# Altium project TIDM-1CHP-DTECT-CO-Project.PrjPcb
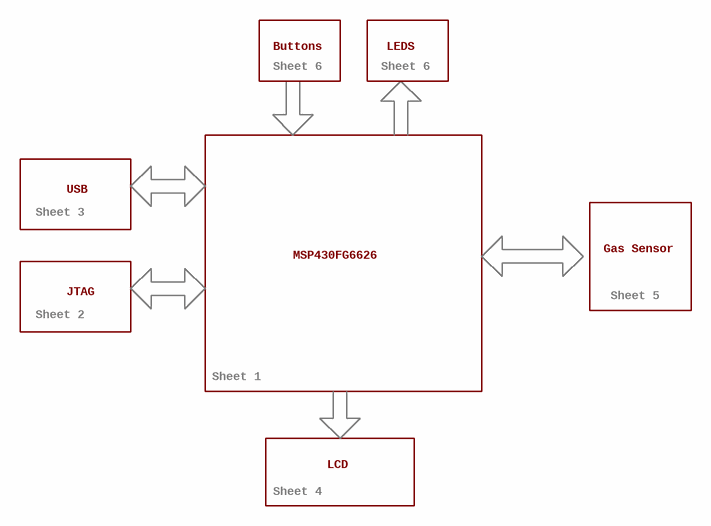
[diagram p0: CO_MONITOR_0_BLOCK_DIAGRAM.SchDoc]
CopyrightYear: 2016; EVM_orderable: Not Orderable; PCB_Layout: Ricardo Zepeda; PCB_Rev: 1.0; PRJ_Customer: Public Release; PRJ_Engineer: Ricardo Zepeda; PRJ_Title: MSP430 Single-Chip, Portable, CO Detector; SCH_Rev: 1.0; TechSupport: http://www.ti.com/support; TID: TIDM-1CHP-DTECT-CO
8 sheets, 116 parts. Net scope: global (net labels, ports and power ports of the same name join across sheets).
Board files: CO_MONITOR_LAYOUT_MAIN.PcbDoc, CO_MONITOR_LAYOUT_BACKUP.PcbDoc
Sheets:
  CO_MONITOR_0_BLOCK_DIAGRAM.SchDoc
  CO_MONITOR_1_MSP430FG6626.SchDoc
  CO_MONITOR_2_JTAG_SBW.SchDoc
  CO_MONITOR_3_USB_SUBCIRCUIT.SchDoc
  CO_MONITOR_4_LCD.SchDoc
  CO_MONITOR_5_GASDETECTION_SUBCIRCUIT.SchDoc
  CO_MONITOR_6_POWER_SUPPLY.SchDoc
  CO_MONITOR_7_MISCELLANEOUS.SchDoc

## Sheet CO_MONITOR_0_BLOCK_DIAGRAM.SchDoc: CO_MONITOR_0_BLOCK_DIAGRAM.SchDoc
size 431 x 279 mm; DrawnBy: Ricardo Zepeda; SheetNumber: 1; SheetTotal: 8; PageSetup: Record=PageOptions¦CenterHorizontal=True¦CenterVertical=True¦PrintScale=1.00¦XCorrection=1.00¦YCorrection=1.00¦PrintKind=0¦BorderSize=5000000¦LeftOffset=0¦BottomOffset=0¦Orientation=2¦PaperLength=1000¦PaperWidth=1000¦Scale=100¦PaperSource=15¦PrintQuality=600¦MediaType=1¦DitherType=10¦PaperKind=Letter¦PrintScaleMode=1

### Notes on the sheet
- Buttons
- Sheet 6
- LEDS
- Sheet 3
- USB
- MSP430FG6626
- Gas Sensor
- Sheet 2
- JTAG
- Sheet 5
- Sheet 1
- LCD
- Sheet 4

## Sheet CO_MONITOR_1_MSP430FG6626.SchDoc: CO_MONITOR_1_MSP430FG6626.SchDoc
size 431 x 279 mm; DrawnBy: Ricardo Zepeda; SheetNumber: 2; SheetTotal: 8; PageSetup: Record=PageOptions¦CenterHorizontal=True¦CenterVertical=True¦PrintScale=1.00¦XCorrection=1.00¦YCorrection=1.00¦PrintKind=0¦BorderSize=5000000¦LeftOffset=0¦BottomOffset=0¦Orientation=2¦PaperLength=1000¦PaperWidth=1000¦Scale=100¦PaperSource=15¦PrintQuality=600¦MediaType=1¦DitherType=10¦PaperKind=Letter¦PrintScaleMode=1
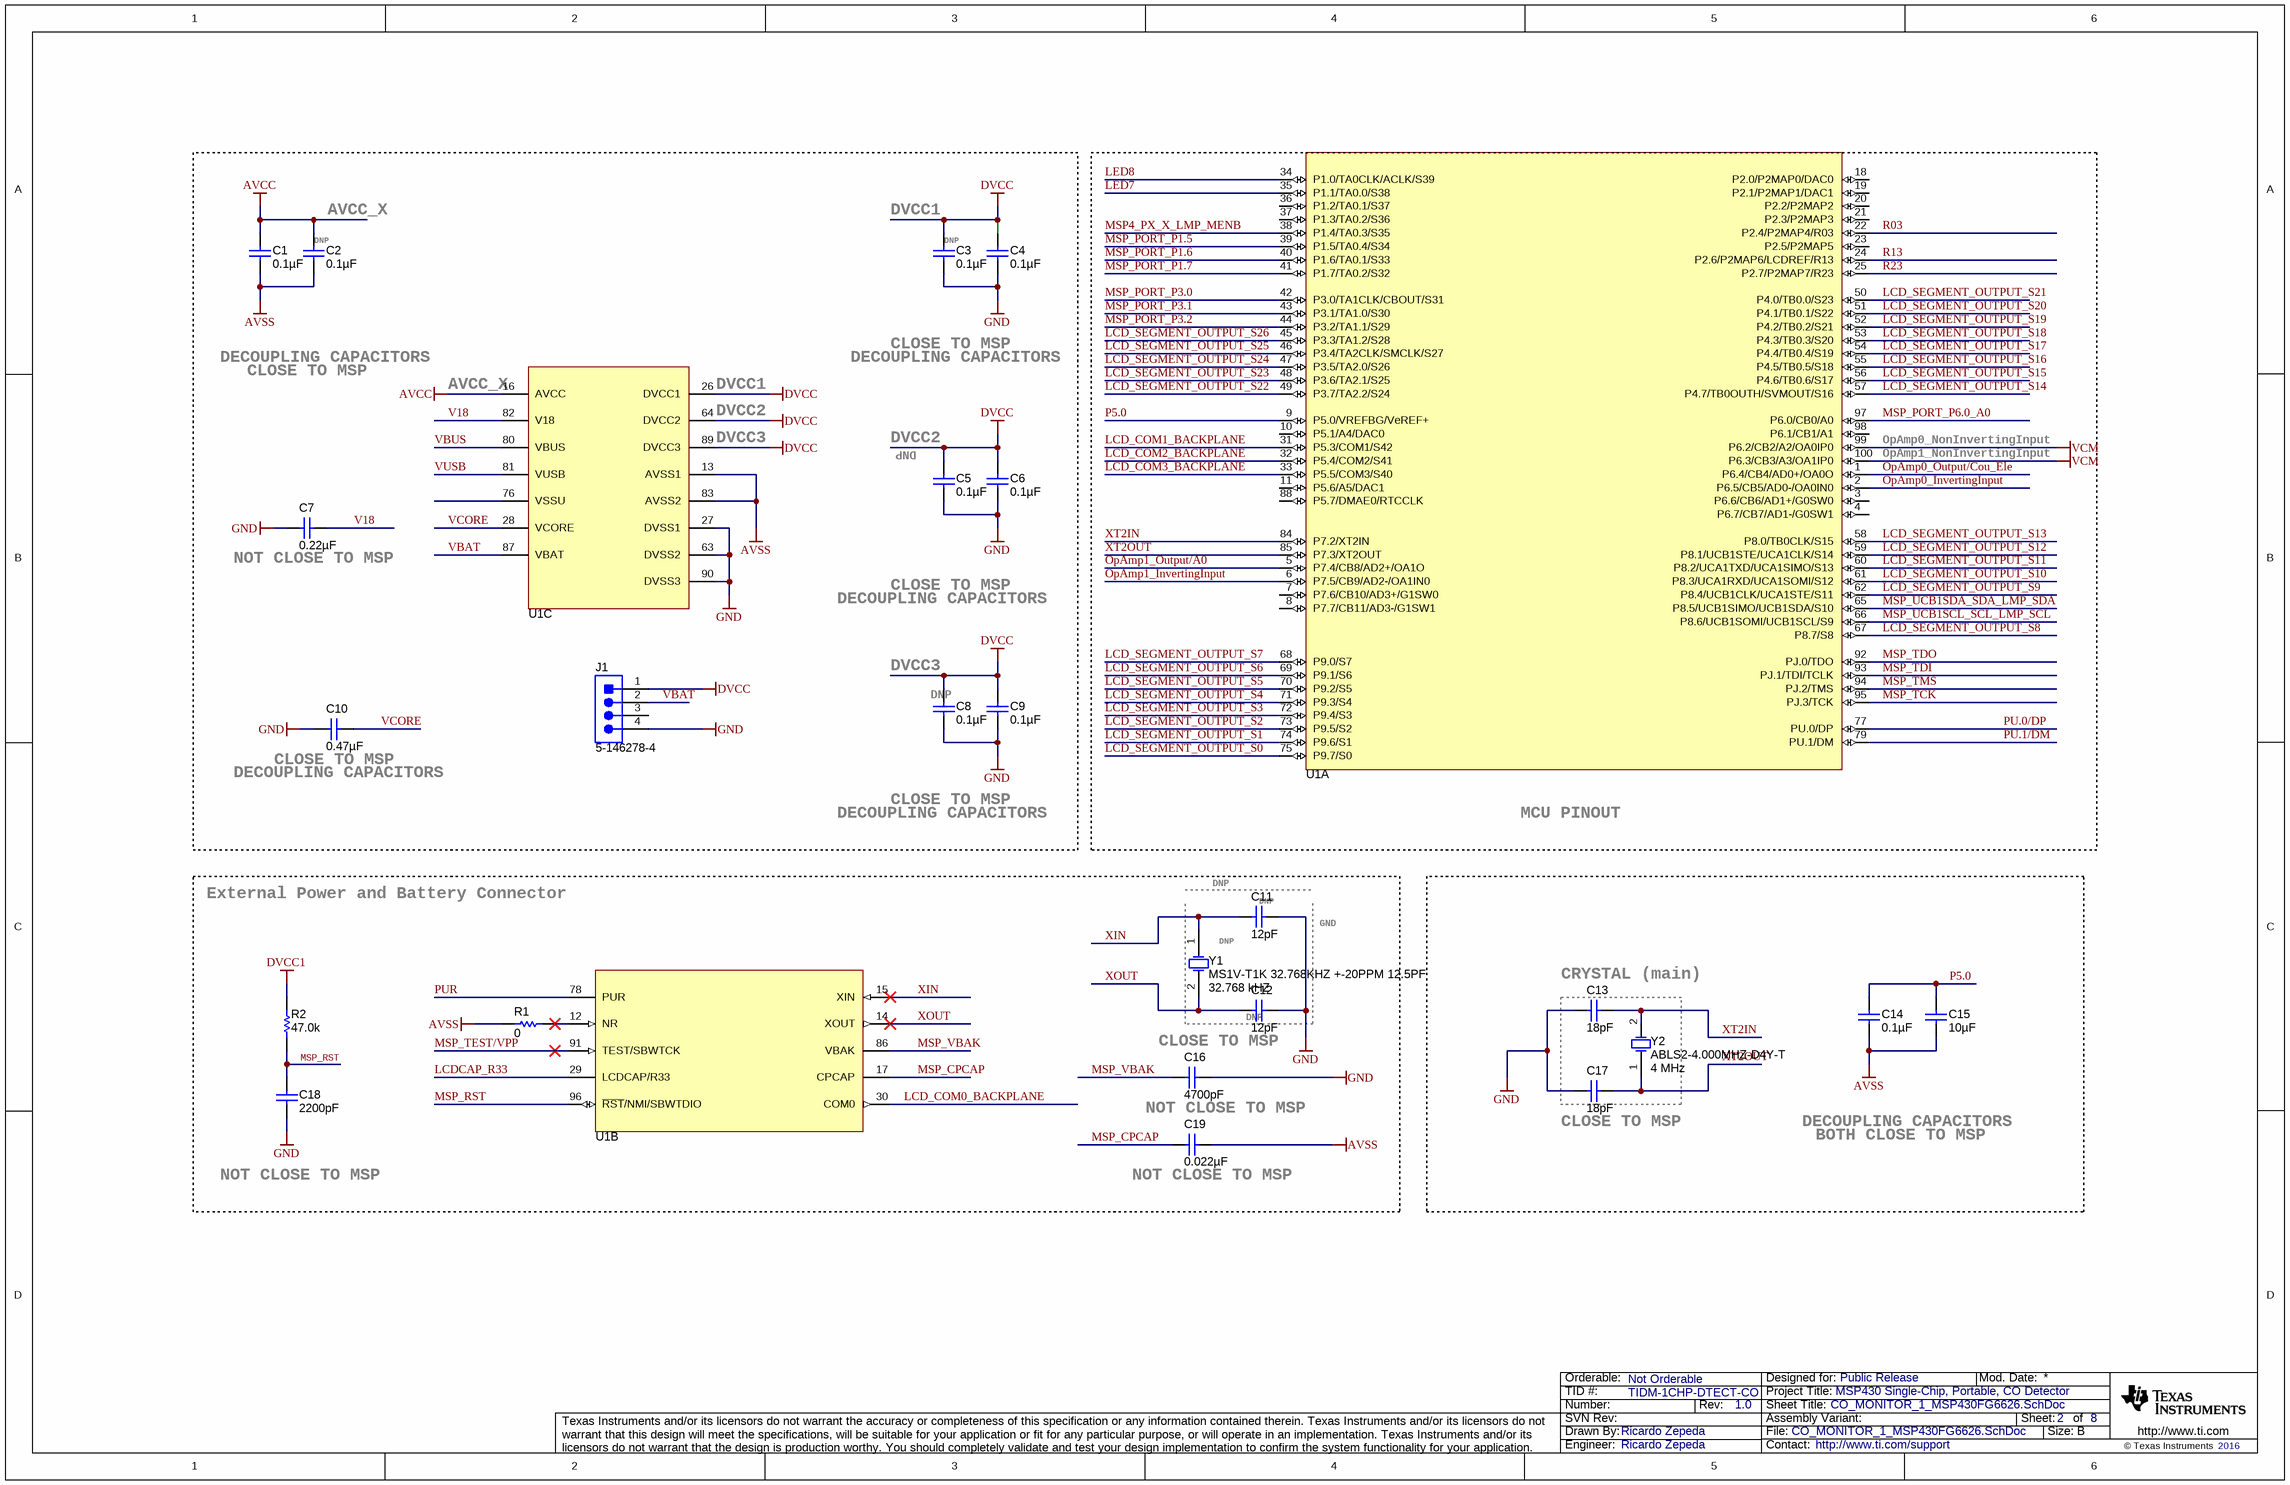
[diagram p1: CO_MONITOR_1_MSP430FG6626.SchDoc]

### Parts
C1  ValueDisplayed: 0.1µF  [1206_190]  (hidden comment: C3216NP01H104J160AA)
C2  ValueDisplayed: 0.1µF  [1206_190]  (hidden comment: C3216NP01H104J160AA)
C3  ValueDisplayed: 0.1µF  [1206_190]  (hidden comment: C3216NP01H104J160AA)
C4  ValueDisplayed: 0.1µF  [1206_190]  (hidden comment: C3216NP01H104J160AA)
C5  ValueDisplayed: 0.1µF  [1206_190]  (hidden comment: C3216NP01H104J160AA)
C6  ValueDisplayed: 0.1µF  [1206_190]  (hidden comment: C3216NP01H104J160AA)
C7  ValueDisplayed: 0.22µF  [0603]  (hidden comment: C1608X7R1H224K080AB)
C8  ValueDisplayed: 0.1µF  [1206_190]  (hidden comment: C3216NP01H104J160AA)
C9  ValueDisplayed: 0.1µF  [1206_190]  (hidden comment: C3216NP01H104J160AA)
C10  ValueDisplayed: 0.47µF  [0603]  (hidden comment: GRM188R61C474KA93D)
C11  ValueDisplayed: 12pF  [0603]  (hidden comment: C1608C0G1H120J)
C12  ValueDisplayed: 12pF  [0603]  (hidden comment: C1608C0G1H120J)
C13  ValueDisplayed: 18pF  [0805]  (hidden comment: C0805C180J5GACTU)
C14  ValueDisplayed: 0.1µF  [1206_190]  (hidden comment: C3216NP01H104J160AA)
C15  ValueDisplayed: 10µF  [0603]  (hidden comment: GRM188R60J106ME84)
C16  ValueDisplayed: 4700pF  [0603]  (hidden comment: C0603C472J5RACTU)
C17  ValueDisplayed: 18pF  [0805]  (hidden comment: C0805C180J5GACTU)
C18  ValueDisplayed: 2200pF  [0603]  (hidden comment: GRM188R71C222KA01D)
C19  ValueDisplayed: 0.022µF  [0603]  (hidden comment: GRM188R71H223KA01D)
J1  5-146278-4  [TE_5-146278-4]
R1  ValueDisplayed: 0  [0603]  (hidden comment: CRCW06030000Z0EA)
R2  ValueDisplayed: 47.0k  [0603]  (hidden comment: RT0603BRD0747KL)
U1  MSP430FG6626IPZR  [PZ0100A_N]  (value not drawn)  (parts A,B,C of 3)
Y1  MS1V-T1K 32.768KHZ +-20PPM 12.5PF  Frequency: 32.768 kHZ  [XTAL_MS1V-T1K]
Y2  ABLS2-4.000MHZ-D4Y-T  Frequency: 4 MHz  [ABRACON_ABLS2]

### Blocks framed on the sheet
MCU PINOUT: U1
CRYSTAL (main): C13 C17 Y2

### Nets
AVCC: C1.1 C2.1 U1.16(AVCC)
AVSS: C1.2 C2.2 C14.2 C15.2 C19.1 R1.1 U1.13(AVSS1) U1.83(AVSS2)
DVCC: C3.1 C4.1 C5.1 C6.1 C8.1 C9.1 J1.1 U1.26(DVCC1) U1.64(DVCC2) U1.89(DVCC3)
DVCC1: R2.2
GND: C3.2 C4.2 C5.2 C6.2 C7.2 C8.2 C9.2 C10.2 C11.1 C12.1 C13.2 C16.1 C17.2 C18.2 J1.4 U1.27(DVSS1) U1.63(DVSS2) U1.90(DVSS3)
VCM: U1.99(P6.2/CB2/A2/OA0IP0) U1.100(P6.3/CB3/A3/OA1IP0)
LCD_COM0_BACKPLANE: U1.30(COM0)
LCD_COM1_BACKPLANE: U1.31(P5.3/COM1/S42)
LCD_COM2_BACKPLANE: U1.32(P5.4/COM2/S41)
LCD_COM3_BACKPLANE: U1.33(P5.5/COM3/S40)
LCD_SEGMENT_OUTPUT_S0: U1.75(P9.7/S0)
LCD_SEGMENT_OUTPUT_S1: U1.74(P9.6/S1)
LCD_SEGMENT_OUTPUT_S2: U1.73(P9.5/S2)
LCD_SEGMENT_OUTPUT_S3: U1.72(P9.4/S3)
LCD_SEGMENT_OUTPUT_S4: U1.71(P9.3/S4)
LCD_SEGMENT_OUTPUT_S5: U1.70(P9.2/S5)
LCD_SEGMENT_OUTPUT_S6: U1.69(P9.1/S6)
LCD_SEGMENT_OUTPUT_S7: U1.68(P9.0/S7)
LCD_SEGMENT_OUTPUT_S8: U1.67(P8.7/S8)
LCD_SEGMENT_OUTPUT_S9: U1.62(P8.4/UCB1CLK/UCA1STE/S11)
LCD_SEGMENT_OUTPUT_S10: U1.61(P8.3/UCA1RXD/UCA1SOMI/S12)
LCD_SEGMENT_OUTPUT_S11: U1.60(P8.2/UCA1TXD/UCA1SIMO/S13)
LCD_SEGMENT_OUTPUT_S12: U1.59(P8.1/UCB1STE/UCA1CLK/S14)
LCD_SEGMENT_OUTPUT_S13: U1.58(P8.0/TB0CLK/S15)
LCD_SEGMENT_OUTPUT_S14: U1.57(P4.7/TB0OUTH/SVMOUT/S16)
LCD_SEGMENT_OUTPUT_S15: U1.56(P4.6/TB0.6/S17)
LCD_SEGMENT_OUTPUT_S16: U1.55(P4.5/TB0.5/S18)
LCD_SEGMENT_OUTPUT_S17: U1.54(P4.4/TB0.4/S19)
LCD_SEGMENT_OUTPUT_S18: U1.53(P4.3/TB0.3/S20)
LCD_SEGMENT_OUTPUT_S19: U1.52(P4.2/TB0.2/S21)
LCD_SEGMENT_OUTPUT_S20: U1.51(P4.1/TB0.1/S22)
LCD_SEGMENT_OUTPUT_S21: U1.50(P4.0/TB0.0/S23)
LCD_SEGMENT_OUTPUT_S22: U1.49(P3.7/TA2.2/S24)
LCD_SEGMENT_OUTPUT_S23: U1.48(P3.6/TA2.1/S25)
LCD_SEGMENT_OUTPUT_S24: U1.47(P3.5/TA2.0/S26)
LCD_SEGMENT_OUTPUT_S25: U1.46(P3.4/TA2CLK/SMCLK/S27)
LCD_SEGMENT_OUTPUT_S26: U1.45(P3.3/TA1.2/S28)
LCDCAP_R33: U1.29(LCDCAP/R33)
LED7: U1.35(P1.1/TA0.0/S38)
LED8: U1.34(P1.0/TA0CLK/ACLK/S39)
MSP4_PX_X_LMP_MENB: U1.38(P1.4/TA0.3/S35)
MSP_CPCAP: C19.2 U1.17(CPCAP)
MSP_PORT_P1.5: U1.39(P1.5/TA0.4/S34)
MSP_PORT_P1.6: U1.40(P1.6/TA0.1/S33)
MSP_PORT_P1.7: U1.41(P1.7/TA0.2/S32)
MSP_PORT_P3.0: U1.42(P3.0/TA1CLK/CBOUT/S31)
MSP_PORT_P3.1: U1.43(P3.1/TA1.0/S30)
MSP_PORT_P3.2: U1.44(P3.2/TA1.1/S29)
MSP_PORT_P6.0_A0: U1.97(P6.0/CB0/A0)
MSP_RST: C18.1 R2.1 U1.96(~{RST}/NMI/SBWTDIO)
MSP_TCK: U1.95(PJ.3/TCK)
MSP_TDI: U1.93(PJ.1/TDI/TCLK)
MSP_TDO: U1.92(PJ.0/TDO)
MSP_TEST/VPP: U1.91(TEST/SBWTCK)
MSP_TMS: U1.94(PJ.2/TMS)
MSP_UCB1SCL_SCL_LMP_SCL: U1.66(P8.6/UCB1SOMI/UCB1SCL/S9)
MSP_UCB1SDA_SDA_LMP_SDA: U1.65(P8.5/UCB1SIMO/UCB1SDA/S10)
MSP_VBAK: C16.2 U1.86(VBAK)
OpAmp0_InvertingInput: U1.2(P6.5/CB5/AD0-/OA0IN0)
OpAmp0_Output/Cou_Ele: U1.1(P6.4/CB4/AD0+/OA0O)
OpAmp1_InvertingInput: U1.6(P7.5/CB9/AD2-/OA1IN0)
OpAmp1_Output/A0: U1.5(P7.4/CB8/AD2+/OA1O)
P5.0: C14.1 C15.1 U1.9(P5.0/VREFBG/VeREF+)
PU.0/DP: U1.77(PU.0/DP)
PU.1/DM: U1.79(PU.1/DM)
PUR: U1.78(PUR)
R03: U1.22(P2.4/P2MAP4/R03)
R13: U1.24(P2.6/P2MAP6/LCDREF/R13)
R23: U1.25(P2.7/P2MAP7/R23)
V18: C7.1 U1.82(V18)
VBAT: J1.2 U1.87(VBAT)
VBUS: U1.80(VBUS)
VCORE: C10.1 U1.28(VCORE)
VUSB: U1.81(VUSB)
XIN: C11.2 U1.15(XIN) Y1.1(OSC1)
XOUT: C12.2 U1.14(XOUT) Y1.2(OSC2)
XT2IN: C13.1 U1.84(P7.2/XT2IN) Y2.2(OSC2)
XT2OUT: C17.1 U1.85(P7.3/XT2OUT) Y2.1(OSC1)
NetR1_2: R1.2 U1.12(NR)

Not connected (* = marked no-connect by the designer): J1 3; U1 3(P6.6/CB6/AD1+/G0SW0) 4(P6.7/CB7/AD1-/G0SW1) 7(P7.6/CB10/AD3+/G1SW0) 8(P7.7/CB11/AD3-/G1SW1) 10(P5.1/A4/DAC0) 11(P5.6/A5/DAC1) 18(P2.0/P2MAP0/DAC0) 19(P2.1/P2MAP1/DAC1) 20(P2.2/P2MAP2) 21(P2.3/P2MAP3) 23(P2.5/P2MAP5) 36(P1.2/TA0.1/S37) 37(P1.3/TA0.2/S36) 76(VSSU) 88(P5.7/DMAE0/RTCCLK) 98(P6.1/CB1/A1)

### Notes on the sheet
- (near C2) AVCC_X
- (near C3) DVCC1
- (near C2) DNP
- (near C3) DNP
- DECOUPLING CAPACITORS
- CLOSE TO MSP
- (near U1) AVCC_X
- (near U1) DVCC1
- (near U1) DVCC2
- (near U1) DVCC3
- (near C5) DVCC2
- (near C5) DNP
- (near U1) OpAmp0_NonInvertingInput
- (near U1) OpAmp1_NonInvertingInput
- (near C7) NOT CLOSE TO MSP
- (near C8) DVCC3
- (near C8) DNP
- (near C10) CLOSE TO MSP
- (near C10) DECOUPLING CAPACITORS
- External Power and Battery Connector
- DNP
- (near C11) DNP
- (near Y1) DNP
- (near C11) GND
- (near C12) DNP
- NOT CLOSE TO MSP
- (near C17) CLOSE TO MSP
- BOTH CLOSE TO MSP
- (near C19) NOT CLOSE TO MSP

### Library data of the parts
C1-C6 C8 C9 C14 = C3216NP01H104J160AA: CAP, CERM, 0.1 µF, 50 V, +/- 5%, C0G/NP0, 1206_190; Manufacturer: TDK; Polarized: N; CompType: Capacitor; Value: 0.1uF; U/M: EA; Cap_F: 0.0000001; Tolerance_%: 5; Value1: Unknown; VDC_V: 50; Value2: 50V; TaMin_C: -55; TaMax_C: 150; Cap_Case: 1206
C7 = C1608X7R1H224K080AB: CAP, CERM, 0.22 µF, 50 V, +/- 10%, X7R, 0603; Manufacturer: TDK; Polarized: N; CompType: Capacitor; Value: 0.22uF; U/M: EA; Cap_F: 0.00000022; Tolerance_%: 10; Value1: Unknown; VDC_V: 50; Value2: 50V; TaMin_C: -55; TaMax_C: 125
C10 = GRM188R61C474KA93D: CAP, CERM, 0.47 µF, 16 V, +/- 10%, X5R, 0603; Manufacturer: MuRata; Polarized: N; CompType: Capacitor; Value: 0.47uF; U/M: EA; Cap_F: 0.00000047; Tolerance_%: 10; Value1: Unknown; VDC_V: 16; Value2: 16V; TaMin_C: -55; TaMax_C: 85
C11 C12 = C1608C0G1H120J: CAP, CERM, 12 pF, 50 V, +/- 5%, C0G/NP0, 0603; Manufacturer: TDK; Polarized: N; CompType: Capacitor; Value: 12pF; U/M: EA; Cap_F: 0.000000000012; Tolerance_%: 5; ESR_ohm: 0.3764; Value1: 0.3764 ohm; VDC_V: 50; Value2: 50V; TaMin_C: -55; TaMax_C: 125
C13 C17 = C0805C180J5GACTU: CAP, CERM, 18 pF, 50 V, +/- 5%, C0G/NP0, 0805; Manufacturer: Kemet; Polarized: N; CompType: Capacitor; Value: 18pF; U/M: EA; Cap_F: 0.000000000018; Tolerance_%: 5; ESR_ohm: 0.193; Value1: 0.193 ohm; VDC_V: 50; Value2: 50V; IRMS_A: 0.38; TaMin_C: -55; TaMax_C: 125
C15 = GRM188R60J106ME84: CAP, CERM, 10 µF, 6.3 V, +/- 20%, X5R, 0603; Manufacturer: MuRata; Polarized: N; CompType: Capacitor; Value: 10uF; U/M: EA; Cap_F: 0.00001; Tolerance_%: 20; Value1: Unknown; VDC_V: 6.3; Value2: 6.3V; TaMin_C: -55; TaMax_C: 85
C16 = C0603C472J5RACTU: CAP, CERM, 4700 pF, 50 V, +/- 5%, X7R, 0603; Manufacturer: Kemet; Polarized: N; CompType: Capacitor; Value: 4700pF; U/M: EA; Cap_F: 0.0000000047; Tolerance_%: 5; Value1: Unknown; VDC_V: 50; Value2: 50V; TaMin_C: -55; TaMax_C: 125
C18 = GRM188R71C222KA01D: CAP, CERM, 2200 pF, 16 V, +/- 10%, X7R, 0603; Manufacturer: MuRata; Polarized: N; CompType: Capacitor; Value: 2200pF; U/M: EA; Cap_F: 0.0000000022; Tolerance_%: 10; Value1: Unknown; VDC_V: 16; Value2: 16V; TaMin_C: -55; TaMax_C: 125
C19 = GRM188R71H223KA01D: CAP, CERM, 0.022 µF, 50 V, +/- 10%, X7R, 0603; Manufacturer: MuRata; Polarized: N; CompType: Capacitor; Value: 0.022uF; U/M: EA; Cap_F: 0.000000022; Tolerance_%: 10; Value1: Unknown; VDC_V: 50; Value2: 50V; TaMin_C: -55; TaMax_C: 125
J1 = 5-146278-4: Header, 100mil, 4x1, Tin, TH; Manufacturer: TE Connectivity; SymbolCreator: a0412235; U/M: EA
R1 = CRCW06030000Z0EA: RES, 0, 5%, 0.1 W, 0603; Manufacturer: Vishay-Dale; CompType: Resistor; Value: 0; Value_Code: 0000; Tolerance_%: 5; Power_W: 0.1; Value2: 0.1W; VDC_V: 75; TempCo: 200 ppm/C; EIA_Code: E24; U/M: EA
R2 = RT0603BRD0747KL: RES, 47.0 k, 0.1%, 0.1 W, 0603; Manufacturer: Yageo America; CompType: Resistor; Value: 47.0k; Res_ohm: 47000; Value_Code: 47k0; Tolerance_%: 0.1; Value2: 0.1W; VDC_V: 75; TempCo: 25 ppm/C; EIA_Code: E192; U/M: EA
U1 = MSP430FG6626IPZR: Mixed-Signal Microcontrollers, PZ0100A; Manufacturer: Texas Instruments; SymbolCreator: Altium; CompType: IC; U/M: EA
Y1 = MS1V-T1K 32.768KHZ +-20PPM 12.5PF: Tuning Fork Crystal, 32.768 kHz, 12.5 pF, SMD; Manufacturer: Micro Crystal AG; SymbolCreator: a0412235; U/M: EA; TaMin_C: -40; TaMax_C: 85; Frequency Stability: ±20ppm
Y2 = ABLS2-4.000MHZ-D4Y-T: Crystal, 4MHz, 18pF, SMD; Manufacturer: Abracon Corportation; SymbolCreator: a0412235; U/M: EA; TaMin_C: -40; TaMax_C: 85; Frequency Stability: ±30ppm

## Sheet CO_MONITOR_2_JTAG_SBW.SchDoc: CO_MONITOR_2_JTAG_SBW.SchDoc
size 431 x 279 mm; DrawnBy: Ricardo Zepeda; SheetNumber: 3; SheetTotal: 8; PageSetup: Record=PageOptions¦CenterHorizontal=True¦CenterVertical=True¦PrintScale=1.00¦XCorrection=1.00¦YCorrection=1.00¦PrintKind=0¦BorderSize=5000000¦LeftOffset=0¦BottomOffset=0¦Orientation=2¦PaperLength=1000¦PaperWidth=1000¦Scale=100¦PaperSource=15¦PrintQuality=600¦MediaType=1¦DitherType=10¦PaperKind=Letter¦PrintScaleMode=1
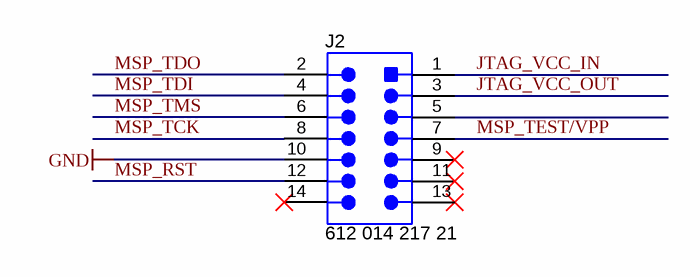
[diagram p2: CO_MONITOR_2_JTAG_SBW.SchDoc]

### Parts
J2  612 014 217 21  [WURTH_612_014_217_21]

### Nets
GND: J2.10
JTAG_VCC_IN: J2.1
JTAG_VCC_OUT: J2.3
MSP_RST: J2.12
MSP_TCK: J2.8
MSP_TDI: J2.4
MSP_TDO: J2.2
MSP_TEST/VPP: J2.7
MSP_TMS: J2.6

Not connected (* = marked no-connect by the designer): J2 5 9* 11* 13* 14*

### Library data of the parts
J2 = 612 014 217 21: Header (Shrouded), 2.54 mm, 7x2, Gold, R/A, TH; Manufacturer: Wurth Elektronik eiSos; SymbolCreator: a0412235; U/M: EA

## Sheet CO_MONITOR_3_USB_SUBCIRCUIT.SchDoc: CO_MONITOR_3_USB_SUBCIRCUIT.SchDoc
size 431 x 279 mm; DrawnBy: Ricardo Zepeda; SheetNumber: 4; SheetTotal: 8; PageSetup: Record=PageOptions¦CenterHorizontal=True¦CenterVertical=True¦PrintScale=1.00¦XCorrection=1.00¦YCorrection=1.00¦PrintKind=0¦BorderSize=5000000¦LeftOffset=0¦BottomOffset=0¦Orientation=2¦PaperLength=1000¦PaperWidth=1000¦Scale=100¦PaperSource=15¦PrintQuality=600¦MediaType=1¦DitherType=10¦PaperKind=Letter¦PrintScaleMode=1
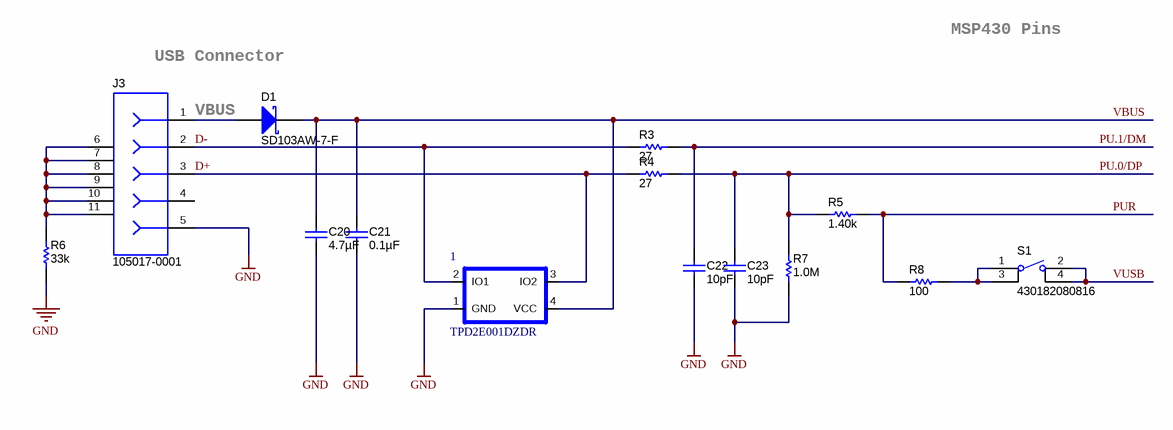
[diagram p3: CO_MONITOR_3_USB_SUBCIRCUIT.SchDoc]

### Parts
1  TPD2E001DZDR  [DZD]
C20  ValueDisplayed: 4.7µF  [0805]  (hidden comment: GRM21BC81E475KA12L)
C21  ValueDisplayed: 0.1µF  [0805]  (hidden comment: GRM21BR71H104KA01L)
C22  ValueDisplayed: 10pF  [0805]  (hidden comment: 08055A100JAT2A)
C23  ValueDisplayed: 10pF  [0805]  (hidden comment: 08055A100JAT2A)
D1  SD103AW-7-F  [SOD-123]
J3  105017-0001  [CONN_105017-0001]
R3  ValueDisplayed: 27  [0805_HV]  (hidden comment: CRCW080527R0JNEA)
R4  ValueDisplayed: 27  [0805_HV]  (hidden comment: CRCW080527R0JNEA)
R5  ValueDisplayed: 1.40k  [0805]  (hidden comment: CRCW08051K40FKEA)
R6  ValueDisplayed: 33k  [0805]  (hidden comment: CRCW080533K0JNEA)
R7  ValueDisplayed: 1.0M  [0805]  (hidden comment: CRCW08051M00JNEA)
R8  ValueDisplayed: 100  [0805]  (hidden comment: RT0805BRD07100RL)
S1  430182080816  [SW_430182080816]

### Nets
GND: 1.1(GND) C20.2 C21.2 C22.2 C23.2 J3.5 R6.1 R7.1
D+: 1.3(IO2) J3.3 R4.1
D-: 1.2(IO1) J3.2 R3.1
PU.0/DP: C23.1 R4.2 R5.1 R7.2
PU.1/DM: C22.1 R3.2
PUR: R5.2 R8.1
VBUS: 1.4(VCC) C20.1 C21.1 D1.1(K)
VUSB: S1.2 S1.4
NetD1_2: D1.2(A) J3.1
NetJ3_6: J3.6 J3.7 J3.8 J3.9 J3.10 J3.11 R6.2
NetR8_2: R8.2 S1.1 S1.3

Not connected (* = marked no-connect by the designer): J3 4

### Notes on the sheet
- USB Connector
- MSP430 Pins
- VBUS

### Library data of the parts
1 = TPD2E001DZDR: IC, Low-Capacitacnce 2-Chan ±15-kV ESD-Protection Array; Manufacturer: TI; Alternate Manufacturer: None; Area: 15.96 mm
C20 = GRM21BC81E475KA12L: CAP, CERM, 4.7 µF, 25 V, +/- 10%, X6S, 0805; Manufacturer: MuRata; Polarized: N; CompType: Capacitor; Value: 4.7uF; U/M: EA; Cap_F: 0.0000047; Tolerance_%: 10; Value1: Unknown; VDC_V: 25; Value2: 25V; TaMin_C: -55; TaMax_C: 105
C21 = GRM21BR71H104KA01L: CAP, CERM, 0.1 µF, 50 V, +/- 10%, X7R, 0805; Manufacturer: MuRata; Polarized: N; CompType: Capacitor; Value: 0.1uF; U/M: EA; Cap_F: 0.0000001; Tolerance_%: 10; Value1: Unknown; VDC_V: 50; Value2: 50V; TaMin_C: -55; TaMax_C: 125
C22 C23 = 08055A100JAT2A: CAP, CERM, 10 pF, 50 V, +/- 5%, C0G/NP0, 0805; Manufacturer: AVX; Polarized: N; CompType: Capacitor; Value: 10pF; U/M: EA; Cap_F: 0.00000000001; Tolerance_%: 5; ESR_ohm: 1.561; Value1: 1.561 ohm; VDC_V: 50; Value2: 50V; TaMin_C: -55; TaMax_C: 125
D1 = SD103AW-7-F: Diode, Schottky, 40 V, 0.35 A, SOD-123; Manufacturer: Diodes Inc.; U/M: EA; Vf_V: 0.55; Value: 40V; Value1: 0.35A; Value2: 0.55V; Io_A: 0.35; Vr_V: 40
J3 = 105017-0001: Connector, Receptacle, Micro-USB Type B, R/A, Bottom Mount SMT; Manufacturer: Molex; SymbolCreator: a0412235; U/M: EA
R3 R4 = CRCW080527R0JNEA: RES, 27, 5%, 0.125 W, 0805; Manufacturer: Vishay-Dale; CompType: Resistor; Value: 27; Value_Code: 27R0; Tolerance_%: 5; Power_W: 0.125; Value2: 0.125W; VDC_V: 150; TempCo: 200 ppm/C; EIA_Code: E24; U/M: EA
R5 = CRCW08051K40FKEA: RES, 1.40 k, 1%, 0.125 W, 0805; Manufacturer: Vishay-Dale; CompType: Resistor; Value: 1.40k; Res_ohm: 1400; Value_Code: 1k40; Tolerance_%: 1; Power_W: 0.125; Value2: 0.125W; VDC_V: 150; TempCo: 100 ppm/C; EIA_Code: E96; U/M: EA
R6 = CRCW080533K0JNEA: RES, 33 k, 5%, 0.125 W, 0805; Manufacturer: Vishay-Dale; CompType: Resistor; Value: 33k; Res_ohm: 33000; Value_Code: 33k0; Tolerance_%: 5; Power_W: 0.125; Value2: 0.125W; VDC_V: 150; TempCo: 200 ppm/C; EIA_Code: E24; U/M: EA
R7 = CRCW08051M00JNEA: RES, 1.0 M, 5%, 0.125 W, 0805; Manufacturer: Vishay-Dale; CompType: Resistor; Value: 1.0Meg; Res_ohm: 1000000; Value_Code: 1M00; Tolerance_%: 5; Power_W: 0.125; Value2: 0.125W; VDC_V: 150; TempCo: 200 ppm/C; EIA_Code: E24; U/M: EA
R8 = RT0805BRD07100RL: RES, 100, 0.1%, 0.125 W, 0805; Manufacturer: Yageo America; CompType: Resistor; Value: 100; Value_Code: 100R; Tolerance_%: 0.1; Power_W: 0.125; Value2: 0.125W; VDC_V: 150; TempCo: 25 ppm/C; EIA_Code: E192; U/M: EA
S1 = 430182080816: Switch, Tactile, SPST-NO, 0.05A, 12V, SMD; Manufacturer: Wurth Elektronik; SymbolCreator: Altium; VDC_V: 12; SwitchFunction: Off-Mom; PositionCount: 1; CurrentRating_mA: 50

## Sheet CO_MONITOR_4_LCD.SchDoc: CO_MONITOR_4_LCD.SchDoc
size 431 x 279 mm; DrawnBy: Ricardo Zepeda; SheetNumber: 5; SheetTotal: 8; PageSetup: Record=PageOptions¦CenterHorizontal=True¦CenterVertical=True¦PrintScale=1.00¦XCorrection=1.00¦YCorrection=1.00¦PrintKind=0¦BorderSize=5000000¦LeftOffset=0¦BottomOffset=0¦Orientation=2¦PaperLength=1000¦PaperWidth=1000¦Scale=100¦PaperSource=15¦PrintQuality=600¦MediaType=1¦DitherType=10¦PaperKind=Letter¦PrintScaleMode=1
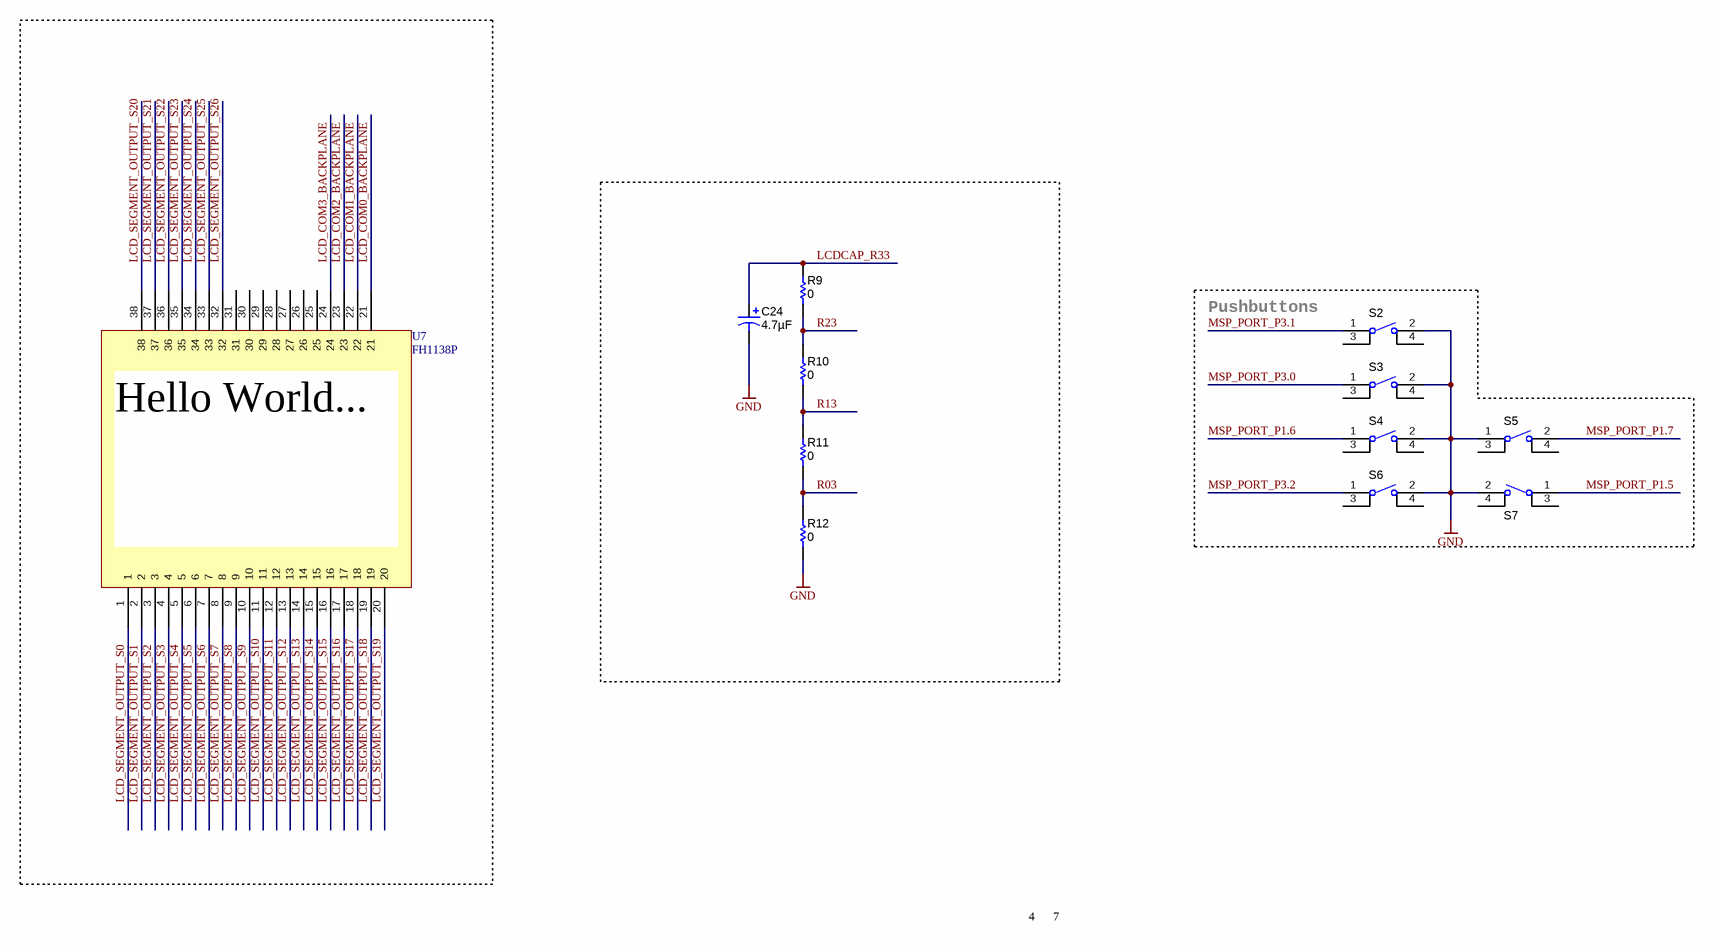
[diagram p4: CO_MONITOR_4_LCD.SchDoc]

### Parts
C24  ValueDisplayed: 4.7µF  [6032-28]  (hidden comment: 293D475X9025C2TE3)
R9  ValueDisplayed: 0  [0603]  (hidden comment: CRCW06030000Z0EA)
R10  ValueDisplayed: 0  [0603]  (hidden comment: CRCW06030000Z0EA)
R11  ValueDisplayed: 0  [0603]  (hidden comment: CRCW06030000Z0EA)
R12  ValueDisplayed: 0  [0603]  (hidden comment: CRCW06030000Z0EA)
S2  430182080816  [SW_430182080816]  (value not drawn)
S3  430182080816  [SW_430182080816]  (value not drawn)
S4  430182080816  [SW_430182080816]  (value not drawn)
S5  430182080816  [SW_430182080816]  (value not drawn)
S6  430182080816  [SW_430182080816]  (value not drawn)
S7  430182080816  [SW_430182080816]  (value not drawn)
U7  FH1138P  [FH1138P]

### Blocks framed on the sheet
Pushbuttons: S2-S7

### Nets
GND: C24.2(-) R12.1 S2.2 S3.2 S4.2 S5.1 S6.2 S7.2
LCD_COM0_BACKPLANE: U7.21
LCD_COM1_BACKPLANE: U7.22
LCD_COM2_BACKPLANE: U7.23
LCD_COM3_BACKPLANE: U7.24
LCD_SEGMENT_OUTPUT_S0: U7.1
LCD_SEGMENT_OUTPUT_S1: U7.2
LCD_SEGMENT_OUTPUT_S2: U7.3
LCD_SEGMENT_OUTPUT_S3: U7.4
LCD_SEGMENT_OUTPUT_S4: U7.5
LCD_SEGMENT_OUTPUT_S5: U7.6
LCD_SEGMENT_OUTPUT_S6: U7.7
LCD_SEGMENT_OUTPUT_S7: U7.8
LCD_SEGMENT_OUTPUT_S8: U7.9
LCD_SEGMENT_OUTPUT_S9: U7.10
LCD_SEGMENT_OUTPUT_S10: U7.11
LCD_SEGMENT_OUTPUT_S11: U7.12
LCD_SEGMENT_OUTPUT_S12: U7.13
LCD_SEGMENT_OUTPUT_S13: U7.14
LCD_SEGMENT_OUTPUT_S14: U7.15
LCD_SEGMENT_OUTPUT_S15: U7.16
LCD_SEGMENT_OUTPUT_S16: U7.17
LCD_SEGMENT_OUTPUT_S17: U7.18
LCD_SEGMENT_OUTPUT_S18: U7.19
LCD_SEGMENT_OUTPUT_S19: U7.20
LCD_SEGMENT_OUTPUT_S20: U7.38
LCD_SEGMENT_OUTPUT_S21: U7.37
LCD_SEGMENT_OUTPUT_S22: U7.36
LCD_SEGMENT_OUTPUT_S23: U7.35
LCD_SEGMENT_OUTPUT_S24: U7.34
LCD_SEGMENT_OUTPUT_S25: U7.33
LCD_SEGMENT_OUTPUT_S26: U7.32
LCDCAP_R33: C24.1(+) R9.2
MSP_PORT_P1.5: S7.1
MSP_PORT_P1.6: S4.1
MSP_PORT_P1.7: S5.2
MSP_PORT_P3.0: S3.1
MSP_PORT_P3.1: S2.1
MSP_PORT_P3.2: S6.1
R03: R11.1 R12.2
R13: R10.1 R11.2
R23: R9.1 R10.2

Not connected (* = marked no-connect by the designer): S2 3 4; S3 3 4; S4 3 4; S5 3 4; S6 3 4; S7 3 4; U7 25 26 27 28 29 30 31

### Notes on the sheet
- 4
- 7

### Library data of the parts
C24 = 293D475X9025C2TE3: CAP, TA, 4.7 µF, 25 V, +/- 10%, 2 ohm, SMD; Manufacturer: Vishay-Sprague; Polarized: Y; CompType: Capacitor; Value: 4.7uF; U/M: EA; Cap_F: 0.0000047; Tolerance_%: 10; Value1: 2 ohm; VDC_V: 25; Value2: 25V; ESR_ohm: 2; IRMS_A: 0.24; TaMin_C: -55; TaMax_C: 125; Cap_Case: C
R9-R12 = CRCW06030000Z0EA: as R1 on sheet CO_MONITOR_1_MSP430FG6626
S2-S7 = 430182080816: as S1 on sheet CO_MONITOR_3_USB_SUBCIRCUIT

## Sheet CO_MONITOR_5_GASDETECTION_SUBCIRCUIT.SchDoc: CO_MONITOR_5_GASDETECTION_SUBCIRCUIT.SchDoc
size 431 x 279 mm; DrawnBy: Ricardo Zepeda; SheetNumber: 6; SheetTotal: 8; PageSetup: Record=PageOptions¦CenterHorizontal=True¦CenterVertical=True¦PrintScale=1.00¦XCorrection=1.00¦YCorrection=1.00¦PrintKind=0¦BorderSize=5000000¦LeftOffset=0¦BottomOffset=0¦Orientation=2¦PaperLength=1000¦PaperWidth=1000¦Scale=100¦PaperSource=15¦PrintQuality=600¦MediaType=1¦DitherType=10¦PaperKind=Letter¦PrintScaleMode=1
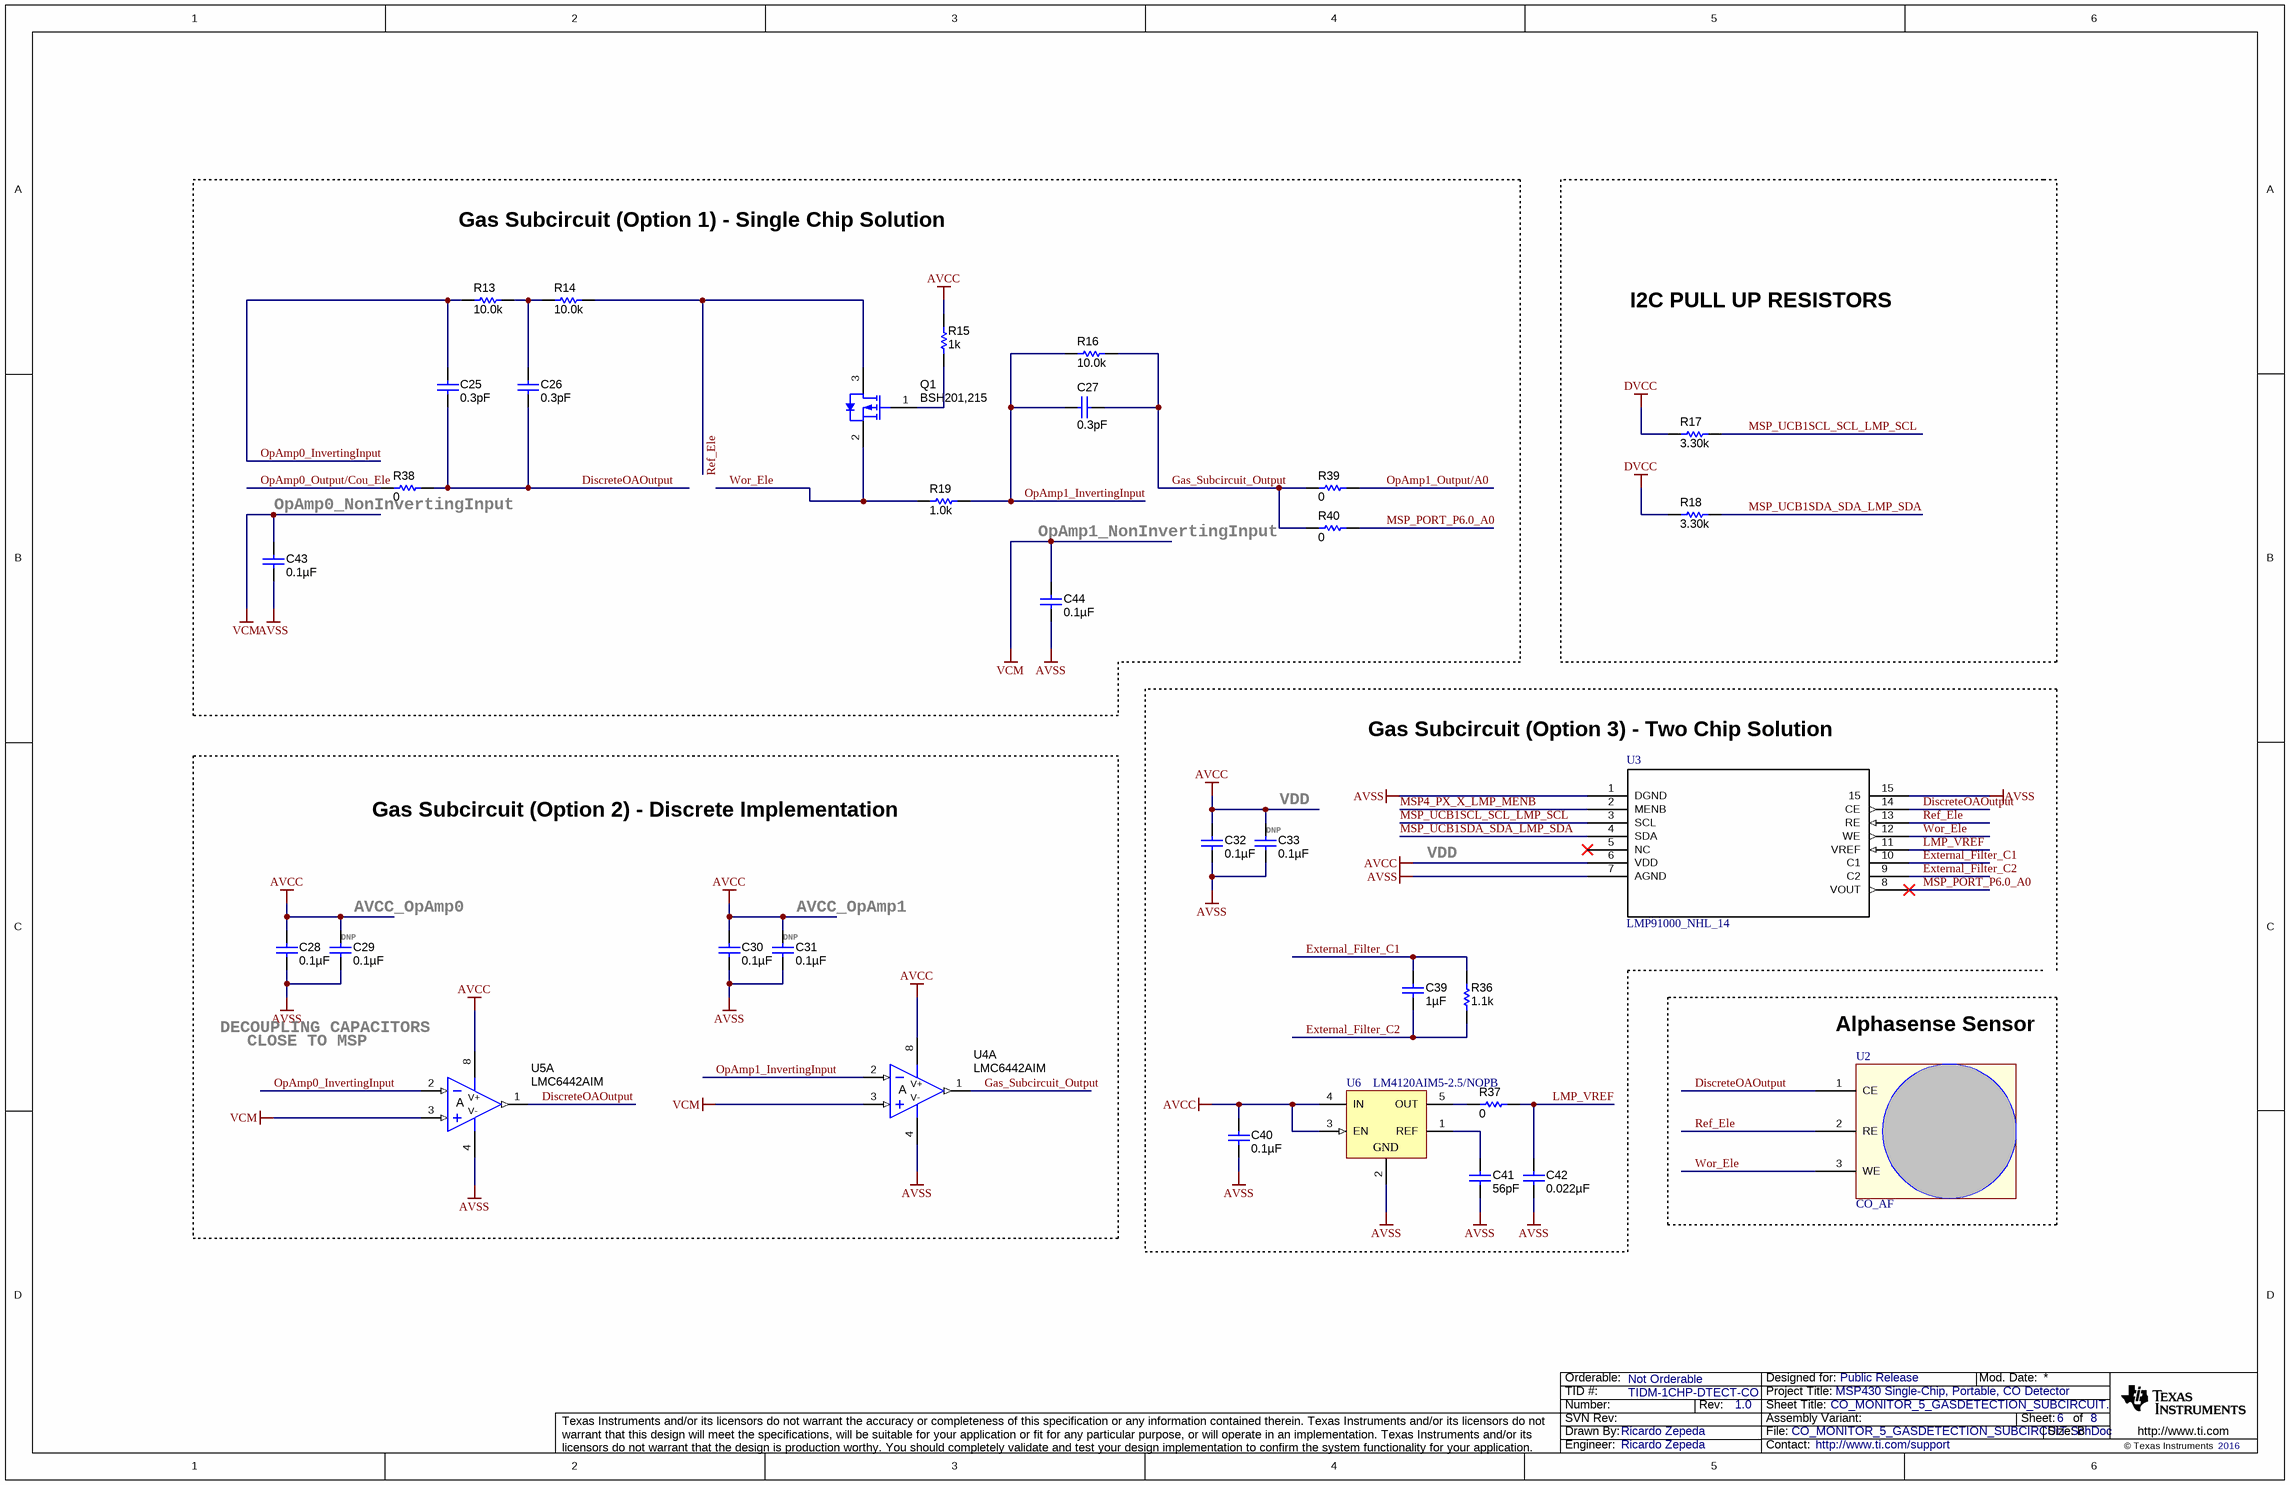
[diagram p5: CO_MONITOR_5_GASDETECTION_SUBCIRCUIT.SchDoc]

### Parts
C25  ValueDisplayed: 0.3pF  [0402]  (hidden comment: 500R07S0R3BV4T)
C26  ValueDisplayed: 0.3pF  [0402]  (hidden comment: 500R07S0R3BV4T)
C27  ValueDisplayed: 0.3pF  [0402]  (hidden comment: 500R07S0R3BV4T)
C28  ValueDisplayed: 0.1µF  [0805]  (hidden comment: 08055C104JAT2A)
C29  ValueDisplayed: 0.1µF  [0805]  (hidden comment: 08055C104JAT2A)
C30  ValueDisplayed: 0.1µF  [0805]  (hidden comment: 08055C104JAT2A)
C31  ValueDisplayed: 0.1µF  [0805]  (hidden comment: 08055C104JAT2A)
C32  ValueDisplayed: 0.1µF  [0805]  (hidden comment: 08055C104JAT2A)
C33  ValueDisplayed: 0.1µF  [0805]  (hidden comment: 08055C104JAT2A)
C39  ValueDisplayed: 1µF  [0805]  (hidden comment: C0805C105K4RACTU)
C40  ValueDisplayed: 0.1µF  [0805]  (hidden comment: 08055C104JAT2A)
C41  ValueDisplayed: 56pF  [0805]  (hidden comment: 08055A560JAT2A)
C42  ValueDisplayed: 0.022µF  [0805]  (hidden comment: 08055C223KAT2A)
C43  ValueDisplayed: 0.1µF  [0805]  (hidden comment: 08055C104JAT2A)
C44  ValueDisplayed: 0.1µF  [0805]  (hidden comment: 08055C104JAT2A)
Q1  BSH201,215  [SOT-23]
R13  ValueDisplayed: 10.0k  [0805]  (hidden comment: RG2012P-103-B-T5)
R14  ValueDisplayed: 10.0k  [0805]  (hidden comment: RG2012P-103-B-T5)
R15  ValueDisplayed: 1k  [0603]  (hidden comment: CRCW060310K0FKEA)
R16  ValueDisplayed: 10.0k  [0805]  (hidden comment: RG2012P-103-B-T5)
R17  ValueDisplayed: 3.30k  [0805_HV]  (hidden comment: RG2012P-332-B-T5)
R18  ValueDisplayed: 3.30k  [0805_HV]  (hidden comment: RG2012P-332-B-T5)
R19  ValueDisplayed: 1.0k  [0805]  (hidden comment: ERJ-6GEYJ102V)
R36  ValueDisplayed: 1.1k  [0805]  (hidden comment: CRCW08051K10JNEA)
R37  ValueDisplayed: 0  [0805]  (hidden comment: CRCW08050000Z0EA)
R38  ValueDisplayed: 0  [0805]  (hidden comment: CRCW08050000Z0EA)
R39  ValueDisplayed: 0  [0805]  (hidden comment: CRCW08050000Z0EA)
R40  ValueDisplayed: 0  [0805]  (hidden comment: CRCW08050000Z0EA)
U2  CO_AF  [CO_AF]
U3  LMP91000_NHL_14  [SDA14B]
U4  LMC6442AIM  [D0008A_N]  (part A of 2)
U5  LMC6442AIM  [D0008A_N]  (part A of 2)
U6  LM4120AIM5-2.5/NOPB  [MF05A_N]

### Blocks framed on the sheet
Gas Subcircuit (Option 1) - Single Chip Solution: C25-C27 C43 C44 Q1 R13-R16 R19 R38-R40
I2C PULL UP RESISTORS: R17 R18
Gas Subcircuit (Option 2) - Discrete Implementation: C28-C31 U4 U5
Alphasense Sensor: U2

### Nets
AVCC: C28.1 C29.1 C30.1 C31.1 C32.1 C33.1 C40.1 R15.2 U3.6(VDD) U4.8(V+) U5.8(V+) U6.3(EN) U6.4(IN)
AVSS: C28.2 C29.2 C30.2 C31.2 C32.2 C33.2 C40.2 C41.2 C42.2 C43.2 C44.2 U3.1(DGND) U3.7(AGND) U3.15 U4.4(V-) U5.4(V-) U6.2(GND)
DVCC: R17.1 R18.1
VCM: C43.1 C44.1 U4.3(IN+) U5.3(IN+)
DiscreteOAOutput: C25.2 C26.2 R38.2 U2.1(CE) U3.14(CE) U5.1(OUT)
External_Filter_C1: C39.1 R36.2 U3.10(C1)
External_Filter_C2: C39.2 R36.1 U3.9(C2)
Gas_Subcircuit_Output: C27.2 R16.1 R39.1 R40.1 U4.1(OUT)
LMP_VREF: C42.1 R37.2 U3.11(VREF)
MSP4_PX_X_LMP_MENB: U3.2(MENB)
MSP_PORT_P6.0_A0: R40.2 U3.8(VOUT)
MSP_UCB1SCL_SCL_LMP_SCL: R17.2 U3.3(SCL)
MSP_UCB1SDA_SDA_LMP_SDA: R18.2 U3.4(SDA)
OpAmp0_InvertingInput: C25.1 R13.2 U5.2(IN-)
OpAmp0_Output/Cou_Ele: R38.1
OpAmp1_InvertingInput: C27.1 R16.2 R19.2 U4.2(IN-)
OpAmp1_Output/A0: R39.2
Ref_Ele: Q1.3(D) R14.1 U2.2(RE) U3.13(RE)
Wor_Ele: Q1.2(S) R19.1 U2.3(WE) U3.12(WE)
NetC26_1: C26.1 R13.1 R14.2
NetC41_1: C41.1 U6.1(REF)
NetQ1_1: Q1.1(G) R15.1
NetR37_1: R37.1 U6.5(OUT)

Not connected (* = marked no-connect by the designer): U3 5(NC)*

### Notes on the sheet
- (near R38) OpAmp0_NonInvertingInput
- OpAmp1_NonInvertingInput
- Gas Subcircuit (Option 3) - Two Chip Solution
- (near C33) DNP
- (near C33) VDD
- VDD
- (near C29) DNP
- (near C29) AVCC_OpAmp0
- (near C31) DNP
- (near C31) AVCC_OpAmp1
- DECOUPLING CAPACITORS
- CLOSE TO MSP

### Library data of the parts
C25-C27 = 500R07S0R3BV4T: CAP, CERM, 0.3 pF, 50 V, +/- 30%, C0G/NP0, 0402; Manufacturer: Johanson Technology; Polarized: N; CompType: Capacitor; Value: 0.3pF; U/M: EA; Cap_F: 0.0000000000003; Tolerance_%: 30; Value1: Unknown; VDC_V: 50; Value2: 50V; TaMin_C: -55; TaMax_C: 125
C28-C33 C40 C43 C44 = 08055C104JAT2A: CAP, CERM, 0.1 µF, 50 V, +/- 5%, X7R, 0805; Manufacturer: AVX; Polarized: N; CompType: Capacitor; Value: 0.1uF; U/M: EA; Cap_F: 0.0000001; Tolerance_%: 5; ESR_ohm: 0.024; Value1: 0.024 ohm; VDC_V: 50; Value2: 50V; TaMin_C: -55; TaMax_C: 125
C39 = C0805C105K4RACTU: CAP, CERM, 1 µF, 16 V, +/- 10%, X7R, 0805; Manufacturer: Kemet; Polarized: N; CompType: Capacitor; Value: 1uF; U/M: EA; Cap_F: 0.000001; Tolerance_%: 10; ESR_ohm: 0.015; Value1: 0.015 ohm; VDC_V: 16; Value2: 16V; IRMS_A: 8.19; TaMin_C: -55; TaMax_C: 125
C41 = 08055A560JAT2A: CAP, CERM, 56 pF, 50 V, +/- 5%, C0G/NP0, 0805; Manufacturer: AVX; Polarized: N; CompType: Capacitor; Value: 56pF; U/M: EA; Cap_F: 0.000000000056; Tolerance_%: 5; ESR_ohm: 0.508; Value1: 0.508 ohm; VDC_V: 50; Value2: 50V; TaMin_C: -55; TaMax_C: 125
C42 = 08055C223KAT2A: CAP, CERM, 0.022 µF, 50 V, +/- 10%, X7R, 0805; Manufacturer: AVX; Polarized: N; CompType: Capacitor; Value: 0.022uF; U/M: EA; Cap_F: 0.000000022; Tolerance_%: 10; ESR_ohm: 0.052; Value1: 0.052 ohm; VDC_V: 50; Value2: 50V; TaMin_C: -55; TaMax_C: 125
Q1 = BSH201,215: MOSFET, P-CH, -60 V, -0.3 A, SOT-23; Manufacturer: NXP Semiconductor; Alternate Manufacturer: None; U/M: EA; ChType: P; Value: -60V; Value1: 2.7 ohm; Rdson45_ohm: 2.7; Value2: 3 nC; QgTyp_nC: 3; Vgs_V: 20
R13 R14 R16 = RG2012P-103-B-T5: RES, 10.0 k, 0.1%, 0.125 W, 0805; Manufacturer: Susumu Co Ltd; CompType: Resistor; Value: 10.0k; Res_ohm: 10000; Value_Code: 10k0; Tolerance_%: 0.1; Power_W: 0.125; Value2: 0.125W; VDC_V: 100; TempCo: 25 ppm/C; EIA_Code: E192; U/M: EA
R15 = CRCW060310K0FKEA: RES, 10.0 k, 1%, 0.1 W, 0603; Manufacturer: Vishay-Dale; CompType: Resistor; Value: 10.0k; Res_ohm: 10000; Value_Code: 10k0; Tolerance_%: 1; Power_W: 0.1; Value2: 0.1W; VDC_V: 75; TempCo: 100 ppm/C; EIA_Code: E96; U/M: EA
R17 R18 = RG2012P-332-B-T5: RES, 3.30 k, 0.1%, 0.125 W, 0805; Manufacturer: Susumu Co Ltd; CompType: Resistor; Value: 3.30k; Res_ohm: 3300; Value_Code: 3k30; Tolerance_%: 0.1; Power_W: 0.125; Value2: 0.125W; VDC_V: 100; TempCo: 25 ppm/C; U/M: EA
R19 = ERJ-6GEYJ102V: RES, 1.0 k, 5%, 0.125 W, 0805; Manufacturer: Panasonic; CompType: Resistor; Value: 1.0k; Res_ohm: 1000; Value_Code: 1k00; Tolerance_%: 5; Power_W: 0.125; Value2: 0.125W; VDC_V: 150; TempCo: 200 ppm/C; EIA_Code: E24; U/M: EA
R36 = CRCW08051K10JNEA: RES, 1.1 k, 5%, 0.125 W, 0805; Manufacturer: Vishay-Dale; CompType: Resistor; Value: 1.1k; Res_ohm: 1100; Value_Code: 1k10; Tolerance_%: 5; Power_W: 0.125; Value2: 0.125W; VDC_V: 150; TempCo: 200 ppm/C; EIA_Code: E24; U/M: EA
R37-R40 = CRCW08050000Z0EA: RES, 0, 5%, 0.125 W, 0805; Manufacturer: Vishay-Dale; CompType: Resistor; Value: 0; Value_Code: 0000; Tolerance_%: 5; Power_W: 0.125; Value2: 0.125W; VDC_V: 150; TempCo: 200 ppm/C; EIA_Code: E24; U/M: EA
U3 = LMP91000_NHL_14: Imported; Manufacturer: Texas Instruments
U4 U5 = LMC6442AIM: Dual Micropower Rail-to-Rail Output Operational Amplifier, D0008A; Manufacturer: Texas Instruments; CompType: OpAmp IC
U6 = LM4120AIM5-2.5/NOPB: Precision Micropower Low Dropout Voltage Reference, 5-pin SOT-23, Pb-Free; Manufacturer: Texas Instruments; PackageTopMarking: R08A*XTT; PowerWise: Y; CompType: Voltage Reference IC

## Sheet CO_MONITOR_6_POWER_SUPPLY.SchDoc: CO_MONITOR_6_POWER_SUPPLY.SchDoc
size 431 x 279 mm; DrawnBy: Ricardo Zepeda; SheetNumber: 7; SheetTotal: 8; PageSetup: Record=PageOptions¦CenterHorizontal=True¦CenterVertical=True¦PrintScale=1.00¦XCorrection=1.00¦YCorrection=1.00¦PrintKind=0¦BorderSize=5000000¦LeftOffset=0¦BottomOffset=0¦Orientation=2¦PaperLength=1000¦PaperWidth=1000¦Scale=100¦PaperSource=15¦PrintQuality=600¦MediaType=1¦DitherType=10¦PaperKind=Letter¦PrintScaleMode=1
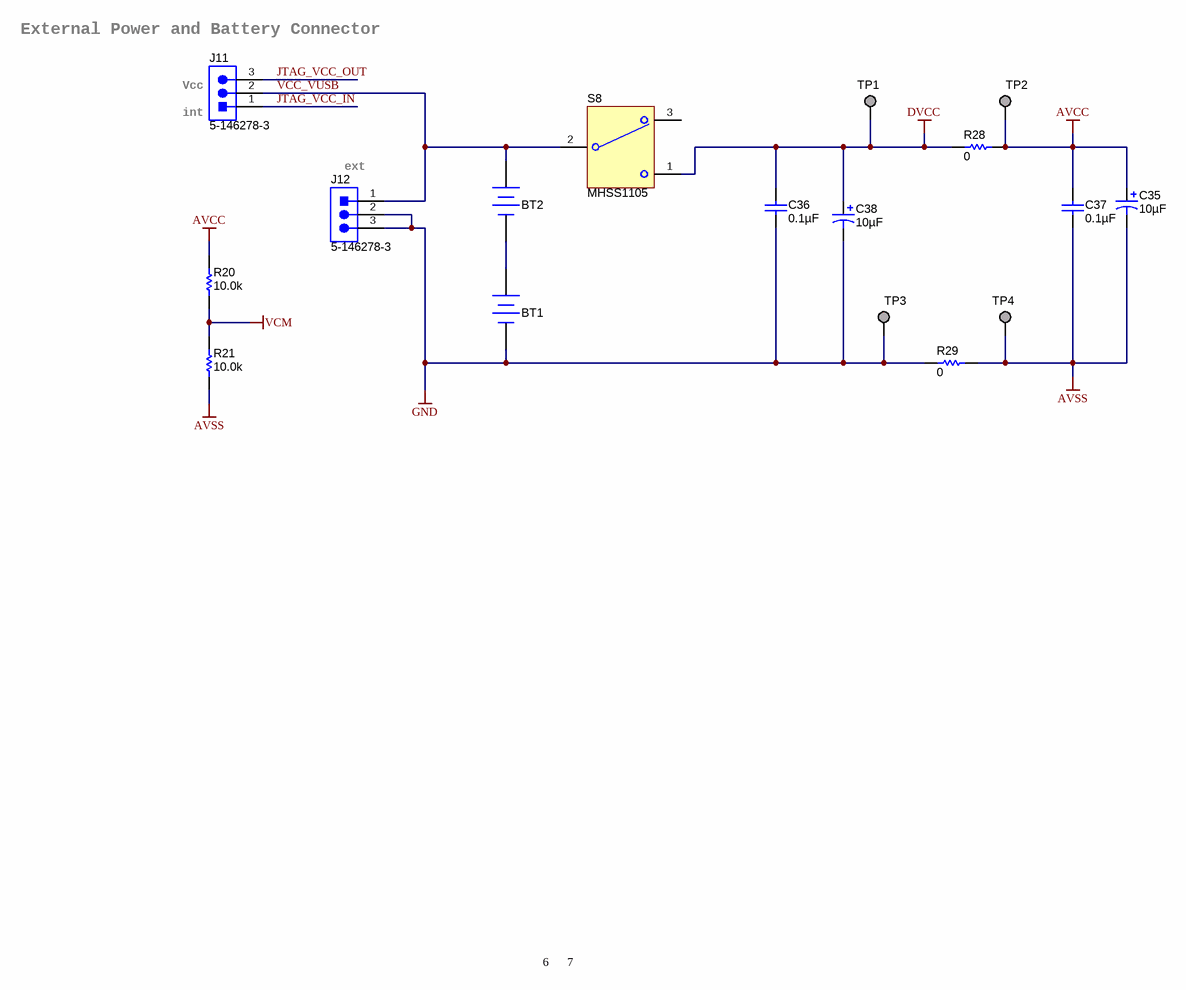
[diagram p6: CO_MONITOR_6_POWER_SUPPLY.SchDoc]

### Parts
BT1  1015  [Keystone_1015]  (value not drawn)
BT2  1015  [Keystone_1015]  (value not drawn)
C35  ValueDisplayed: 10µF  [6032-28]  (hidden comment: 293D106X9020C2TE3)
C36  ValueDisplayed: 0.1µF  [0805]  (hidden comment: C0805C104K4RACTU)
C37  ValueDisplayed: 0.1µF  [0805]  (hidden comment: C0805C104K4RACTU)
C38  ValueDisplayed: 10µF  [6032-28]  (hidden comment: 293D106X9020C2TE3)
J11  5-146278-3  [TE_5-146278-3]
J12  5-146278-3  [TE_5-146278-3]
R20  ValueDisplayed: 10.0k  [0805]  (hidden comment: RG2012P-103-B-T5)
R21  ValueDisplayed: 10.0k  [0805]  (hidden comment: RG2012P-103-B-T5)
R28  ValueDisplayed: 0  [0805]  (hidden comment: CRCW08050000Z0EA)
R29  ValueDisplayed: 0  [0805]  (hidden comment: CRCW08050000Z0EA)
S8  MHSS1105  [SW_MHSS1105]
TP1  TESTPOINT  [TP_H045P075]  (value not drawn)  (no BOM)
TP2  TESTPOINT  [TP_H045P075]  (value not drawn)  (no BOM)
TP3  TESTPOINT  [TP_H045P075]  (value not drawn)  (no BOM)
TP4  TESTPOINT  [TP_H045P075]  (value not drawn)  (no BOM)

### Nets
AVCC: C35.1(+) C37.1 R20.2 R28.2 TP2.1
AVSS: C35.2(-) C37.2 R21.1 R29.2 TP4.1
DVCC: C36.1 C38.1(+) R28.1 S8.1 TP1.1
GND: BT1.2(-) C36.2 C38.2(-) J12.2 J12.3 R29.1 TP3.1
VCM: R20.1 R21.2
JTAG_VCC_IN: J11.1
JTAG_VCC_OUT: J11.3
VCC_VUSB: BT2.1(+) J11.2 J12.1 S8.2(COM)
NetBT1_1: BT1.1(+) BT2.2(-)

Not connected (* = marked no-connect by the designer): S8 3

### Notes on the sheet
- (near J11) External Power and Battery Connector
- (near J11) Vcc
- (near J11) int
- (near J12) ext
- 6
- 7

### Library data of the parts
BT1 BT2 = 1015: AA Battery Holder, Through-hole mount; Manufacturer: Keystone
C35 C38 = 293D106X9020C2TE3: CAP, TA, 10 µF, 20 V, +/- 10%, 1.7 ohm, SMD; Manufacturer: Vishay-Sprague; Polarized: Y; CompType: Capacitor; Value: 10uF; U/M: EA; Cap_F: 0.00001; Tolerance_%: 10; Value1: 1.7 ohm; VDC_V: 20; Value2: 20V; ESR_ohm: 1.7; IRMS_A: 0.25; TaMin_C: -55; TaMax_C: 125; Cap_Case: C
C36 C37 = C0805C104K4RACTU: CAP, CERM, 0.1 µF, 16 V, +/- 10%, X7R, 0805; Manufacturer: Kemet; Polarized: N; CompType: Capacitor; Value: 0.1uF; U/M: EA; Cap_F: 0.0000001; Tolerance_%: 10; ESR_ohm: 0.064; Value1: 0.064 ohm; VDC_V: 16; Value2: 16V; IRMS_A: 1.64; TaMin_C: -55; TaMax_C: 125
J11 J12 = 5-146278-3: Header, 100mil, 3x1, Tin, TH; Manufacturer: TE Connectivity; SymbolCreator: a0799628; U/M: EA
R20 R21 = RG2012P-103-B-T5: as R13 on sheet CO_MONITOR_5_GASDETECTION_SUBCIRCUIT
R28 R29 = CRCW08050000Z0EA: as R37 on sheet CO_MONITOR_5_GASDETECTION_SUBCIRCUIT
S8 = MHSS1105: Switch, Slide, SPDT, R/A, TH; Manufacturer: APEM; SymbolCreator: x0208326; VDC_V: 6; SwitchFunction: On-On; PositionCount: 2; CurrentRating_mA: 300
TP1-TP4 = TP_H0.45P0.75: Manufacturer: Texas Instruments; CompType: Pad

## Sheet CO_MONITOR_7_MISCELLANEOUS.SchDoc: CO_MONITOR_7_MISCELLANEOUS.SchDoc
size 431 x 279 mm; DrawnBy: Ricardo Zepeda; SheetNumber: 8; SheetTotal: 8; PageSetup: Record=PageOptions¦CenterHorizontal=True¦CenterVertical=True¦PrintScale=1.00¦XCorrection=1.00¦YCorrection=1.00¦PrintKind=0¦BorderSize=5000000¦LeftOffset=0¦BottomOffset=0¦Orientation=2¦PaperLength=1000¦PaperWidth=1000¦Scale=100¦PaperSource=15¦PrintQuality=600¦MediaType=1¦DitherType=10¦PaperKind=Letter¦PrintScaleMode=1
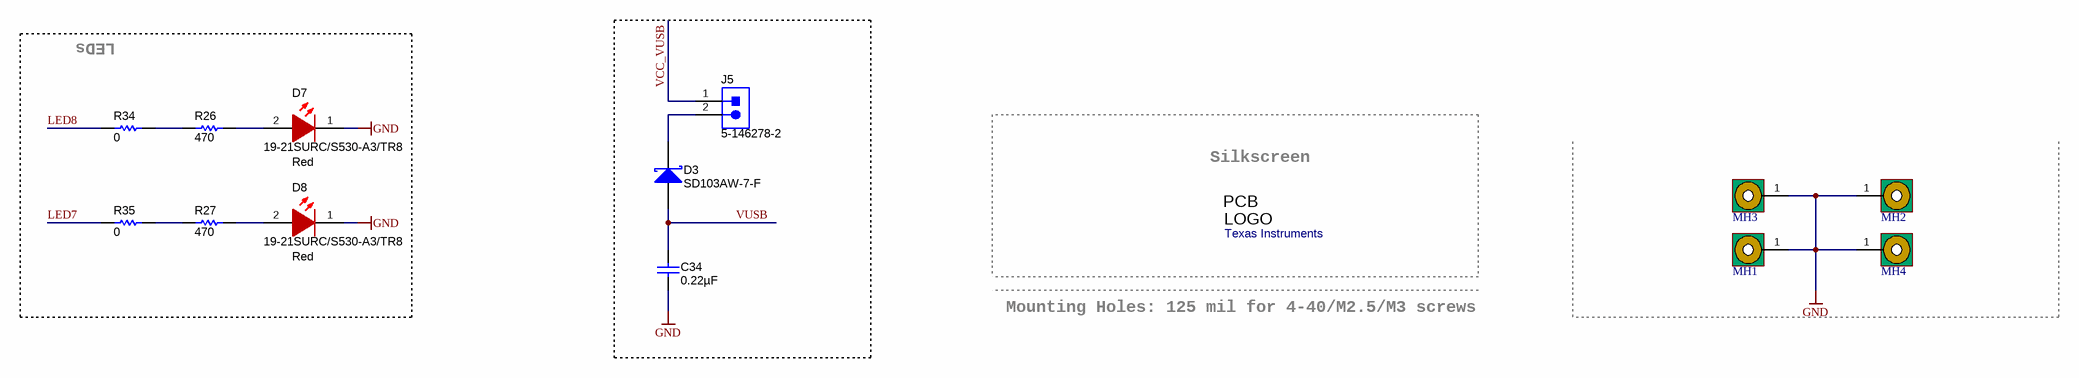
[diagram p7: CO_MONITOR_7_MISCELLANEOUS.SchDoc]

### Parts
C34  ValueDisplayed: 0.22µF  [0805]  (hidden comment: GRM219R71E224KA01D)
D3  SD103AW-7-F  [SOD-123]
D7  19-21SURC/S530-A3/TR8  value Red  [19-21_Red]
D8  19-21SURC/S530-A3/TR8  value Red  [19-21_Red]
J5  5-146278-2  [TE_5-146278-2]
Logo1  Texas Instruments  [TI_Stacked_SolderMask_Medium]  (no BOM)
MH1  MTG_Pads  [MTGP_M3_PanHead]  (value not drawn)  (no BOM)
MH2  MTG_Pads  [MTGP_M3_PanHead]  (value not drawn)  (no BOM)
MH3  MTG_Pads  [MTGP_M3_PanHead]  (value not drawn)  (no BOM)
MH4  MTG_Pads  [MTGP_M3_PanHead]  (value not drawn)  (no BOM)
R26  ValueDisplayed: 470  [0603]  (hidden comment: CRCW0603470RJNEA)
R27  ValueDisplayed: 470  [0603]  (hidden comment: CRCW0603470RJNEA)
R34  ValueDisplayed: 0  [0805_HV]  (hidden comment: MCR10EZPJ000)
R35  ValueDisplayed: 0  [0805_HV]  (hidden comment: MCR10EZPJ000)

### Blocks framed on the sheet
LEDs: D7 D8 R26 R27 R34 R35
Silkscreen: Logo1

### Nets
GND: C34.2 D7.1(K) D8.1(K) MH1.1 MH2.1 MH3.1 MH4.1
LED7: R35.1
LED8: R34.1
VCC_VUSB: J5.1
VUSB: C34.1 D3.2(A)
NetD3_1: D3.1(K) J5.2
NetD7_2: D7.2(A) R26.2
NetD8_2: D8.2(A) R27.2
NetR26_1: R26.1 R34.2
NetR27_1: R27.1 R35.2

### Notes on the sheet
- Mounting Holes: 125 mil for 4-40/M2.5/M3 screws

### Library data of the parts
C34 = GRM219R71E224KA01D: CAP, CERM, 0.22 µF, 25 V, +/- 10%, X7R, 0805; Manufacturer: MuRata; Polarized: N; CompType: Capacitor; Value: 0.22uF; U/M: EA; Cap_F: 0.00000022; Tolerance_%: 10; Value1: Unknown; VDC_V: 25; Value2: 25V; TaMin_C: -55; TaMax_C: 125
D3 = SD103AW-7-F: as D1 on sheet CO_MONITOR_3_USB_SUBCIRCUIT
D7 D8 = 19-21SURC/S530-A3/TR8: LED, Red, SMD; Manufacturer: Everlight; SymbolCreator: Altium; Type: AlInGaP; Vf_V: 2; Value2: 2V; Io_A: 0.02; Vr_V: 5; Ir_A: 1e-005; Tjmax_C: 85; Value1: W; Angle: 100; U/M: EA
J5 = 5-146278-2: Header, 100mil, 2x1, Tin, TH; Manufacturer: TE Connectivity; SymbolCreator: a0412235; U/M: EA
Logo1 = TI_Logo: Texas Instrument Corporate Signature; SymbolCreator: a0412235
MH1-MH4 = Mounting Hole (Metric) with Pads: PCB Mounting Hole; Manufacturer: Any; SymbolCreator: a0412235
R26 R27 = CRCW0603470RJNEA: RES, 470, 5%, 0.1 W, 0603; Manufacturer: Vishay-Dale; CompType: Resistor; Value: 470; Value_Code: 470R; Tolerance_%: 5; Power_W: 0.1; Value2: 0.1W; VDC_V: 75; TempCo: 200 ppm/C; EIA_Code: E24; U/M: EA
R34 R35 = MCR10EZPJ000: RES, 0, 5%, 0.125 W, 0805; Manufacturer: Rohm; CompType: Resistor; Value: 0; Value_Code: 0000; Tolerance_%: 5; Power_W: 0.125; Value2: 0.125W; VDC_V: 150; TempCo: 400 ppm/C; EIA_Code: E24; U/M: EA

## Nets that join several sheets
AVCC: CO_MONITOR_1_MSP430FG6626 (C1.1 C2.1 U1.16), CO_MONITOR_5_GASDETECTION_SUBCIRCUIT (13 pins), CO_MONITOR_6_POWER_SUPPLY (5 pins)
AVSS: CO_MONITOR_1_MSP430FG6626 (8 pins), CO_MONITOR_5_GASDETECTION_SUBCIRCUIT (17 pins), CO_MONITOR_6_POWER_SUPPLY (5 pins)
DVCC: CO_MONITOR_1_MSP430FG6626 (10 pins), CO_MONITOR_5_GASDETECTION_SUBCIRCUIT (R17.1 R18.1), CO_MONITOR_6_POWER_SUPPLY (5 pins)
GND: CO_MONITOR_1_MSP430FG6626 (18 pins), CO_MONITOR_2_JTAG_SBW (J2.10), CO_MONITOR_3_USB_SUBCIRCUIT (8 pins), CO_MONITOR_4_LCD (8 pins), CO_MONITOR_6_POWER_SUPPLY (7 pins), CO_MONITOR_7_MISCELLANEOUS (7 pins)
VCM: CO_MONITOR_1_MSP430FG6626 (U1.99 U1.100), CO_MONITOR_5_GASDETECTION_SUBCIRCUIT (C43.1 C44.1 U4.3 U5.3), CO_MONITOR_6_POWER_SUPPLY (R20.1 R21.2)
JTAG_VCC_IN: CO_MONITOR_2_JTAG_SBW (J2.1), CO_MONITOR_6_POWER_SUPPLY (J11.1)
JTAG_VCC_OUT: CO_MONITOR_2_JTAG_SBW (J2.3), CO_MONITOR_6_POWER_SUPPLY (J11.3)
LCD_COM0_BACKPLANE: CO_MONITOR_1_MSP430FG6626 (U1.30), CO_MONITOR_4_LCD (U7.21)
LCD_COM1_BACKPLANE: CO_MONITOR_1_MSP430FG6626 (U1.31), CO_MONITOR_4_LCD (U7.22)
LCD_COM2_BACKPLANE: CO_MONITOR_1_MSP430FG6626 (U1.32), CO_MONITOR_4_LCD (U7.23)
LCD_COM3_BACKPLANE: CO_MONITOR_1_MSP430FG6626 (U1.33), CO_MONITOR_4_LCD (U7.24)
LCD_SEGMENT_OUTPUT_S0: CO_MONITOR_1_MSP430FG6626 (U1.75), CO_MONITOR_4_LCD (U7.1)
LCD_SEGMENT_OUTPUT_S1: CO_MONITOR_1_MSP430FG6626 (U1.74), CO_MONITOR_4_LCD (U7.2)
LCD_SEGMENT_OUTPUT_S2: CO_MONITOR_1_MSP430FG6626 (U1.73), CO_MONITOR_4_LCD (U7.3)
LCD_SEGMENT_OUTPUT_S3: CO_MONITOR_1_MSP430FG6626 (U1.72), CO_MONITOR_4_LCD (U7.4)
LCD_SEGMENT_OUTPUT_S4: CO_MONITOR_1_MSP430FG6626 (U1.71), CO_MONITOR_4_LCD (U7.5)
LCD_SEGMENT_OUTPUT_S5: CO_MONITOR_1_MSP430FG6626 (U1.70), CO_MONITOR_4_LCD (U7.6)
LCD_SEGMENT_OUTPUT_S6: CO_MONITOR_1_MSP430FG6626 (U1.69), CO_MONITOR_4_LCD (U7.7)
LCD_SEGMENT_OUTPUT_S7: CO_MONITOR_1_MSP430FG6626 (U1.68), CO_MONITOR_4_LCD (U7.8)
LCD_SEGMENT_OUTPUT_S8: CO_MONITOR_1_MSP430FG6626 (U1.67), CO_MONITOR_4_LCD (U7.9)
LCD_SEGMENT_OUTPUT_S9: CO_MONITOR_1_MSP430FG6626 (U1.62), CO_MONITOR_4_LCD (U7.10)
LCD_SEGMENT_OUTPUT_S10: CO_MONITOR_1_MSP430FG6626 (U1.61), CO_MONITOR_4_LCD (U7.11)
LCD_SEGMENT_OUTPUT_S11: CO_MONITOR_1_MSP430FG6626 (U1.60), CO_MONITOR_4_LCD (U7.12)
LCD_SEGMENT_OUTPUT_S12: CO_MONITOR_1_MSP430FG6626 (U1.59), CO_MONITOR_4_LCD (U7.13)
LCD_SEGMENT_OUTPUT_S13: CO_MONITOR_1_MSP430FG6626 (U1.58), CO_MONITOR_4_LCD (U7.14)
LCD_SEGMENT_OUTPUT_S14: CO_MONITOR_1_MSP430FG6626 (U1.57), CO_MONITOR_4_LCD (U7.15)
LCD_SEGMENT_OUTPUT_S15: CO_MONITOR_1_MSP430FG6626 (U1.56), CO_MONITOR_4_LCD (U7.16)
LCD_SEGMENT_OUTPUT_S16: CO_MONITOR_1_MSP430FG6626 (U1.55), CO_MONITOR_4_LCD (U7.17)
LCD_SEGMENT_OUTPUT_S17: CO_MONITOR_1_MSP430FG6626 (U1.54), CO_MONITOR_4_LCD (U7.18)
LCD_SEGMENT_OUTPUT_S18: CO_MONITOR_1_MSP430FG6626 (U1.53), CO_MONITOR_4_LCD (U7.19)
LCD_SEGMENT_OUTPUT_S19: CO_MONITOR_1_MSP430FG6626 (U1.52), CO_MONITOR_4_LCD (U7.20)
LCD_SEGMENT_OUTPUT_S20: CO_MONITOR_1_MSP430FG6626 (U1.51), CO_MONITOR_4_LCD (U7.38)
LCD_SEGMENT_OUTPUT_S21: CO_MONITOR_1_MSP430FG6626 (U1.50), CO_MONITOR_4_LCD (U7.37)
LCD_SEGMENT_OUTPUT_S22: CO_MONITOR_1_MSP430FG6626 (U1.49), CO_MONITOR_4_LCD (U7.36)
LCD_SEGMENT_OUTPUT_S23: CO_MONITOR_1_MSP430FG6626 (U1.48), CO_MONITOR_4_LCD (U7.35)
LCD_SEGMENT_OUTPUT_S24: CO_MONITOR_1_MSP430FG6626 (U1.47), CO_MONITOR_4_LCD (U7.34)
LCD_SEGMENT_OUTPUT_S25: CO_MONITOR_1_MSP430FG6626 (U1.46), CO_MONITOR_4_LCD (U7.33)
LCD_SEGMENT_OUTPUT_S26: CO_MONITOR_1_MSP430FG6626 (U1.45), CO_MONITOR_4_LCD (U7.32)
LCDCAP_R33: CO_MONITOR_1_MSP430FG6626 (U1.29), CO_MONITOR_4_LCD (C24.1 R9.2)
LED7: CO_MONITOR_1_MSP430FG6626 (U1.35), CO_MONITOR_7_MISCELLANEOUS (R35.1)
LED8: CO_MONITOR_1_MSP430FG6626 (U1.34), CO_MONITOR_7_MISCELLANEOUS (R34.1)
MSP4_PX_X_LMP_MENB: CO_MONITOR_1_MSP430FG6626 (U1.38), CO_MONITOR_5_GASDETECTION_SUBCIRCUIT (U3.2)
MSP_PORT_P1.5: CO_MONITOR_1_MSP430FG6626 (U1.39), CO_MONITOR_4_LCD (S7.1)
MSP_PORT_P1.6: CO_MONITOR_1_MSP430FG6626 (U1.40), CO_MONITOR_4_LCD (S4.1)
MSP_PORT_P1.7: CO_MONITOR_1_MSP430FG6626 (U1.41), CO_MONITOR_4_LCD (S5.2)
MSP_PORT_P3.0: CO_MONITOR_1_MSP430FG6626 (U1.42), CO_MONITOR_4_LCD (S3.1)
MSP_PORT_P3.1: CO_MONITOR_1_MSP430FG6626 (U1.43), CO_MONITOR_4_LCD (S2.1)
MSP_PORT_P3.2: CO_MONITOR_1_MSP430FG6626 (U1.44), CO_MONITOR_4_LCD (S6.1)
MSP_PORT_P6.0_A0: CO_MONITOR_1_MSP430FG6626 (U1.97), CO_MONITOR_5_GASDETECTION_SUBCIRCUIT (R40.2 U3.8)
MSP_RST: CO_MONITOR_1_MSP430FG6626 (C18.1 R2.1 U1.96), CO_MONITOR_2_JTAG_SBW (J2.12)
MSP_TCK: CO_MONITOR_1_MSP430FG6626 (U1.95), CO_MONITOR_2_JTAG_SBW (J2.8)
MSP_TDI: CO_MONITOR_1_MSP430FG6626 (U1.93), CO_MONITOR_2_JTAG_SBW (J2.4)
MSP_TDO: CO_MONITOR_1_MSP430FG6626 (U1.92), CO_MONITOR_2_JTAG_SBW (J2.2)
MSP_TEST/VPP: CO_MONITOR_1_MSP430FG6626 (U1.91), CO_MONITOR_2_JTAG_SBW (J2.7)
MSP_TMS: CO_MONITOR_1_MSP430FG6626 (U1.94), CO_MONITOR_2_JTAG_SBW (J2.6)
MSP_UCB1SCL_SCL_LMP_SCL: CO_MONITOR_1_MSP430FG6626 (U1.66), CO_MONITOR_5_GASDETECTION_SUBCIRCUIT (R17.2 U3.3)
MSP_UCB1SDA_SDA_LMP_SDA: CO_MONITOR_1_MSP430FG6626 (U1.65), CO_MONITOR_5_GASDETECTION_SUBCIRCUIT (R18.2 U3.4)
OpAmp0_InvertingInput: CO_MONITOR_1_MSP430FG6626 (U1.2), CO_MONITOR_5_GASDETECTION_SUBCIRCUIT (C25.1 R13.2 U5.2)
OpAmp0_Output/Cou_Ele: CO_MONITOR_1_MSP430FG6626 (U1.1), CO_MONITOR_5_GASDETECTION_SUBCIRCUIT (R38.1)
OpAmp1_InvertingInput: CO_MONITOR_1_MSP430FG6626 (U1.6), CO_MONITOR_5_GASDETECTION_SUBCIRCUIT (C27.1 R16.2 R19.2 U4.2)
OpAmp1_Output/A0: CO_MONITOR_1_MSP430FG6626 (U1.5), CO_MONITOR_5_GASDETECTION_SUBCIRCUIT (R39.2)
PU.0/DP: CO_MONITOR_1_MSP430FG6626 (U1.77), CO_MONITOR_3_USB_SUBCIRCUIT (C23.1 R4.2 R5.1 R7.2)
PU.1/DM: CO_MONITOR_1_MSP430FG6626 (U1.79), CO_MONITOR_3_USB_SUBCIRCUIT (C22.1 R3.2)
PUR: CO_MONITOR_1_MSP430FG6626 (U1.78), CO_MONITOR_3_USB_SUBCIRCUIT (R5.2 R8.1)
R03: CO_MONITOR_1_MSP430FG6626 (U1.22), CO_MONITOR_4_LCD (R11.1 R12.2)
R13: CO_MONITOR_1_MSP430FG6626 (U1.24), CO_MONITOR_4_LCD (R10.1 R11.2)
R23: CO_MONITOR_1_MSP430FG6626 (U1.25), CO_MONITOR_4_LCD (R9.1 R10.2)
VBUS: CO_MONITOR_1_MSP430FG6626 (U1.80), CO_MONITOR_3_USB_SUBCIRCUIT (1.4 C20.1 C21.1 D1.1)
VCC_VUSB: CO_MONITOR_6_POWER_SUPPLY (BT2.1 J11.2 J12.1 S8.2), CO_MONITOR_7_MISCELLANEOUS (J5.1)
VUSB: CO_MONITOR_1_MSP430FG6626 (U1.81), CO_MONITOR_3_USB_SUBCIRCUIT (S1.2 S1.4), CO_MONITOR_7_MISCELLANEOUS (C34.1 D3.2)

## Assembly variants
GAS-DETECTION_Rev0.0: all parts fitted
